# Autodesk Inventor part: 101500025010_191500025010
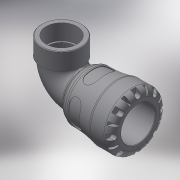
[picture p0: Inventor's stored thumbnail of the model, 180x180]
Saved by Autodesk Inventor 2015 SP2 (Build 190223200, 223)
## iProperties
Created: 2016-12
Part Number: 101500025010_191500025010
Material: Generic
Description: PLASSON 90° ELBOW WITH THREADED FEMALE OFFTAKE 25X1" SERIES 1
Document SubType Name: Modeling
Designer: KIM
Mass: 557.611 g
Surface Area: 990.043 cm^2
Volume: 557.611 cm^3
Density: 1 g/cm^3
Appearance: Default
Author: KIM
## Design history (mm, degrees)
derived "1015.ipt"
feature "Solid1::1015.ipt"
tag "TaggingFeature1"
body "Solid1"
other parameters: "d1" = 20.16, "d2" = 25, "d3" = 31.25, "d4" = 47, "d8" = 41.36, "d13" = 6.3, "d14" = 6.3, "d15" = 0, "d17" = 360 deg, "d19" = 8 deg, "d20" = 0.5, "d21" = 0.5, "d22" = 8 deg, "d24" = 0, "d26" = 360 deg, "d33" = 4.7, "d43" = 38.54, "d51" = 0.47, "d54" = 8.75, "d55" = 5.5, "d57" = 12.348, "d58" = 0, "d74" = 0, "d78" = 48, "d82" = 0.5, "d115" = 360 deg, "d207" = 90 deg, "d228" = 7.4375, "d247" = 0.94, "d248" = 2.88, "d268" = 22.748, "d269" = 2.88, "d270" = 74, "d281" = 4.54365, "d294" = 30.291, "d295" = 21, "d296" = 23.1, "d297" = 27.2619, "d299" = 35.44047, "d300" = 27.2619, "d301" = 0, "d302" = 0, "d303" = 1.54977, "d306" = 0, "d307" = 9, "d308" = 8, "d310" = 3, "d_" = 25, "E_" = 47, "l_" = 48, "A_" = 74, "l_2" = 21, "Rp_" = 30.291, "d9" = 7.875, "d11" = 47, "d12" = 31.25, "d298" = 39.3783
